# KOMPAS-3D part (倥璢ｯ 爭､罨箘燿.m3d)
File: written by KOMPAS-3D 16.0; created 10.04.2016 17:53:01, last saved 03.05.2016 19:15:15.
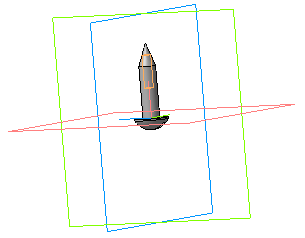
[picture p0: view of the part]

Referenced files in E:\Libs\PartLib\DATA\vault\Methods\Kompas\3D\: PLib_Screw_Shurup_900.m3d
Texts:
  Л63 ГОСТ 15527-2004
  Шуруп 1-4x18.3 ГОСТ 1144-80
  head2
  head4
  groove1
  fillet4
  head3
  groove4
  head5
  fillet1
  groove2
  groove3
  fillet2
  groove5
  head1
  (-) Шуруп 1-4x18.3 ГОСТ 1144-80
